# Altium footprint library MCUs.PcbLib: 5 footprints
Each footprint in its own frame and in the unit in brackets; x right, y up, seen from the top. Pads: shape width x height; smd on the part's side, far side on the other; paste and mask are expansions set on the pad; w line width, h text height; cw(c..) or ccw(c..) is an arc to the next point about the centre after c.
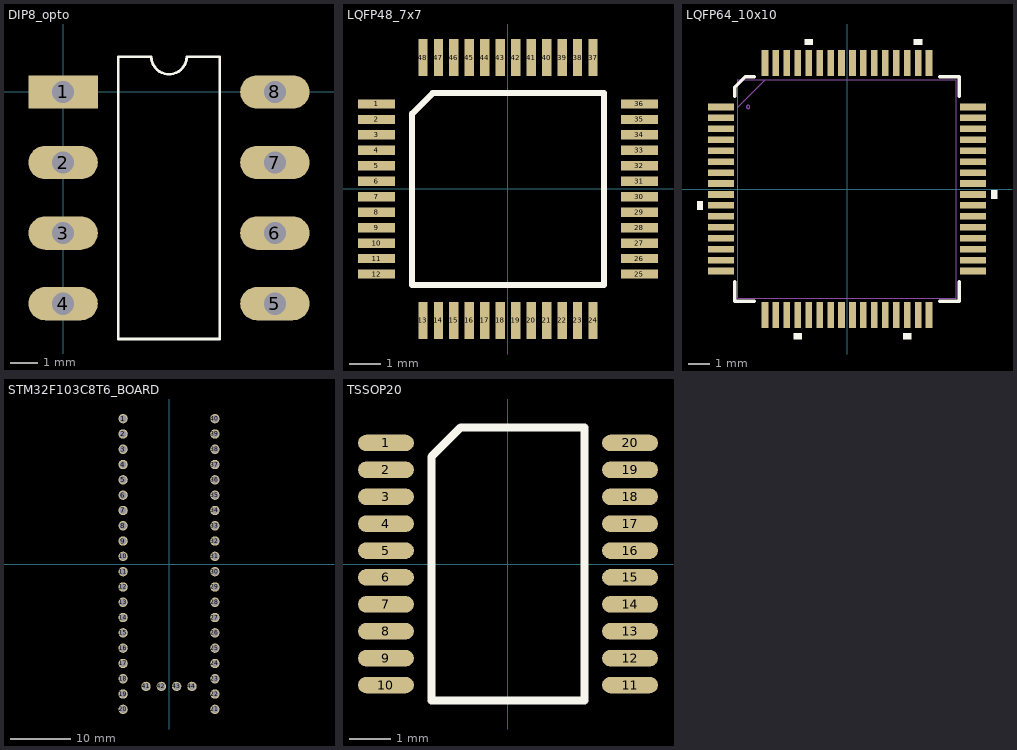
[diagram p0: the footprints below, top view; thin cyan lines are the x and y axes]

## DIP8_opto [mm]
pads (8):
  rect 2.5x1.2 hole 0.8: 1(0,0)
  oval 2.5x1.2 hole 0.8: 2(0,-2.54) 3(0,-5.08) 4(0,-7.62) 5(7.62,-7.62) 6(7.62,-5.08) 7(7.62,-2.54) 8(7.62,0)
Top Overlay:
  lines w0.1: 1.985,-8.89 1.985,1.27 3.175,1.27 ccw(c3.81,1.27) 4.445,1.27 5.635,1.27 5.635,-8.89 1.985,-8.89
3D body "DIP8_opto_w_socket.STEP": height 8.97, standoff -1.6, extent -1.19,-9.135 8.81,1.785

## LQFP48_7x7 [mm]
height 1.6
pads (48):
  rect 1.2x0.3 smd: 1(-4.25,2.75) 2(-4.25,2.25) 3(-4.25,1.75) 4(-4.25,1.25) 5(-4.25,0.75) 6(-4.25,0.25) 7(-4.25,-0.25) 8(-4.25,-0.75) 9(-4.25,-1.25) 10(-4.25,-1.75) 11(-4.25,-2.25) 12(-4.25,-2.75) 25(4.25,-2.75) 26(4.25,-2.25) 27(4.25,-1.75) 28(4.25,-1.25) 29(4.25,-0.75) 30(4.25,-0.25) 31(4.25,0.25) 32(4.25,0.75) 33(4.25,1.25) 34(4.25,1.75) 35(4.25,2.25) 36(4.25,2.75)
  rect 0.3x1.2 smd: 13(-2.75,-4.25) 14(-2.25,-4.25) 15(-1.75,-4.25) 16(-1.25,-4.25) 17(-0.75,-4.25) 18(-0.25,-4.25) 19(0.25,-4.25) 20(0.75,-4.25) 21(1.25,-4.25) 22(1.75,-4.25) 23(2.25,-4.25) 24(2.75,-4.25) 37(2.75,4.25) 38(2.25,4.25) 39(1.75,4.25) 40(1.25,4.25) 41(0.75,4.25) 42(0.25,4.25) 43(-0.25,4.25) 44(-0.75,4.25) 45(-1.25,4.25) 46(-1.75,4.25) 47(-2.25,4.25) 48(-2.75,4.25)
Top Overlay:
  lines w0.2: -3.1,-3.1 3.1,-3.1 3.1,3.1 -2.437,3.1 -3.1,2.437 -3.1,-3.1
3D body "LQFP48_7x7.step": height 1.6, standoff 0, extent -4.5,-4.5 4.5,4.5

## LQFP64_10x10 [mm]
pads (64):
  rect 1.194x0.305 smd paste+0 mask+0: 1(-5.75,3.75) 2(-5.75,3.25) 3(-5.75,2.75) 4(-5.75,2.25) 5(-5.75,1.75) 6(-5.75,1.25) 7(-5.75,0.75) 8(-5.75,0.25) 9(-5.75,-0.25) 10(-5.75,-0.75) 11(-5.75,-1.25) 12(-5.75,-1.75) 13(-5.75,-2.25) 14(-5.75,-2.75) 15(-5.75,-3.25) 16(-5.75,-3.75) 33(5.75,-3.75) 34(5.75,-3.25) 35(5.75,-2.75) 36(5.75,-2.25) 37(5.75,-1.75) 38(5.75,-1.25) 39(5.75,-0.75) 40(5.75,-0.25) 41(5.75,0.25) 42(5.75,0.75) 43(5.75,1.25) 44(5.75,1.75) 45(5.75,2.25) 46(5.75,2.75) 47(5.75,3.25) 48(5.75,3.75)
  rect 0.305x1.194 smd paste+0 mask+0: 17(-3.75,-5.75) 18(-3.25,-5.75) 19(-2.75,-5.75) 20(-2.25,-5.75) 21(-1.75,-5.75) 22(-1.25,-5.75) 23(-0.75,-5.75) 24(-0.25,-5.75) 25(0.25,-5.75) 26(0.75,-5.75) 27(1.25,-5.75) 28(1.75,-5.75) 29(2.25,-5.75) 30(2.75,-5.75) 31(3.25,-5.75) 32(3.75,-5.75) 49(3.75,5.75) 50(3.25,5.75) 51(2.75,5.75) 52(2.25,5.75) 53(1.75,5.75) 54(1.25,5.75) 55(0.75,5.75) 56(0.25,5.75) 57(-0.25,5.75) 58(-0.75,5.75) 59(-1.25,5.75) 60(-1.75,5.75) 61(-2.25,5.75) 62(-2.75,5.75) 63(-3.25,5.75) 64(-3.75,5.75)
Top Overlay:
  region: -6.601,-0.56 -6.855,-0.56 -6.855,-0.941 -6.601,-0.941
  region: -2.06,-6.601 -2.441,-6.601 -2.441,-6.855 -2.06,-6.855
  region: 2.94,-6.601 2.559,-6.601 2.559,-6.855 2.94,-6.855
  region: 6.601,-0.059 6.855,-0.059 6.855,-0.44 6.601,-0.44
  region: 3.441,6.601 3.06,6.601 3.06,6.855 3.441,6.855
  region: -1.559,6.601 -1.94,6.601 -1.94,6.855 -1.559,6.855
  lines w0.152: -5.131,-4.234 -5.131,-5.131 -4.234,-5.131 ; -5.131,4.234 -5.131,4.648 -4.648,5.131 -4.234,5.131 ; 4.234,-5.131 5.131,-5.131 5.131,-4.234 ; 4.234,5.131 5.131,5.131 5.131,4.234
Mechanical 13:
  circle w0: c-4.518,3.75 r0.076
  lines w0.025: -5.004,3.734 -3.734,5.004 ; -5.004,-5.004 5.004,-5.004 5.004,5.004 -5.004,5.004 -5.004,-5.004
3D body "LQFP64.step": height 1.6, standoff 0, extent -6,-6 6,6

## STM32F103C8T6_BOARD [mm]
pads (44):
  round 1.55 hole 1.2: 1(-7.62,24.13) 2(-7.62,21.59) 3(-7.62,19.05) 4(-7.62,16.51) 5(-7.62,13.97) 6(-7.62,11.43) 7(-7.62,8.89) 8(-7.62,6.35) 9(-7.62,3.81) 10(-7.62,1.27) 11(-7.62,-1.27) 12(-7.62,-3.81) 13(-7.62,-6.35) 14(-7.62,-8.89) 15(-7.62,-11.43) 16(-7.62,-13.97) 17(-7.62,-16.51) 18(-7.62,-19.05) 19(-7.62,-21.59) 20(-7.62,-24.13) 21(7.62,-24.13) 22(7.62,-21.59) 23(7.62,-19.05) 24(7.62,-16.51) 25(7.62,-13.97) 26(7.62,-11.43) 27(7.62,-8.89) 28(7.62,-6.35) 29(7.62,-3.81) 30(7.62,-1.27) 31(7.62,1.27) 32(7.62,3.81) 33(7.62,6.35) 34(7.62,8.89) 35(7.62,11.43) 36(7.62,13.97) 37(7.62,16.51) 38(7.62,19.05) 39(7.62,21.59) 40(7.62,24.13) 41(-3.81,-20.32) 42(-1.27,-20.32) 43(1.27,-20.32) 44(3.81,-20.32)
3D body "STM32F103C8T6_Blue_Pill.stp": height 12.32, standoff -5.95, extent -11.43,-29.972 11.43,27.588

## TSSOP20 [mm] "TSSOP, 20-Leads, Body 6,50x4,40mm, Pitch 0,65mm"
pads (20):
  oval 1.35x0.4 smd mask+0.05: 1(-2.95,2.925) 2(-2.95,2.275) 3(-2.95,1.625) 4(-2.95,0.975) 5(-2.95,0.325) 6(-2.95,-0.325) 7(-2.95,-0.975) 8(-2.95,-1.625) 9(-2.95,-2.275) 10(-2.95,-2.925) 11(2.95,-2.925) 12(2.95,-2.275) 13(2.95,-1.625) 14(2.95,-0.975) 15(2.95,-0.325) 16(2.95,0.325) 17(2.95,0.975) 18(2.95,1.625) 19(2.95,2.275) 20(2.95,2.925)
Top Overlay:
  lines w0.2: -1.85,-3.3 1.85,-3.3 1.85,3.3 -1.145,3.3 -1.85,2.595 -1.85,-3.3
3D body "TSSOP20.step": height 1.2, standoff 0, extent -3.2,-3.3 3.2,3.3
